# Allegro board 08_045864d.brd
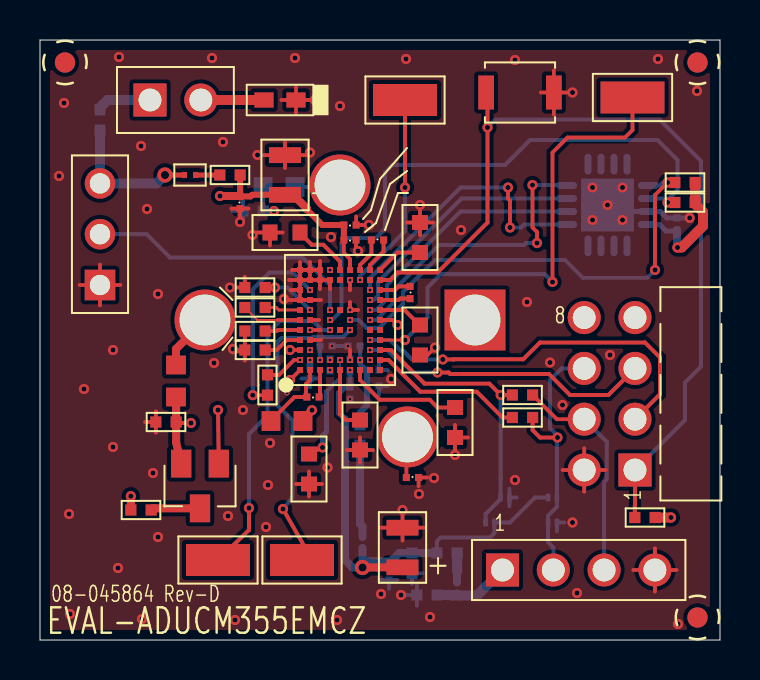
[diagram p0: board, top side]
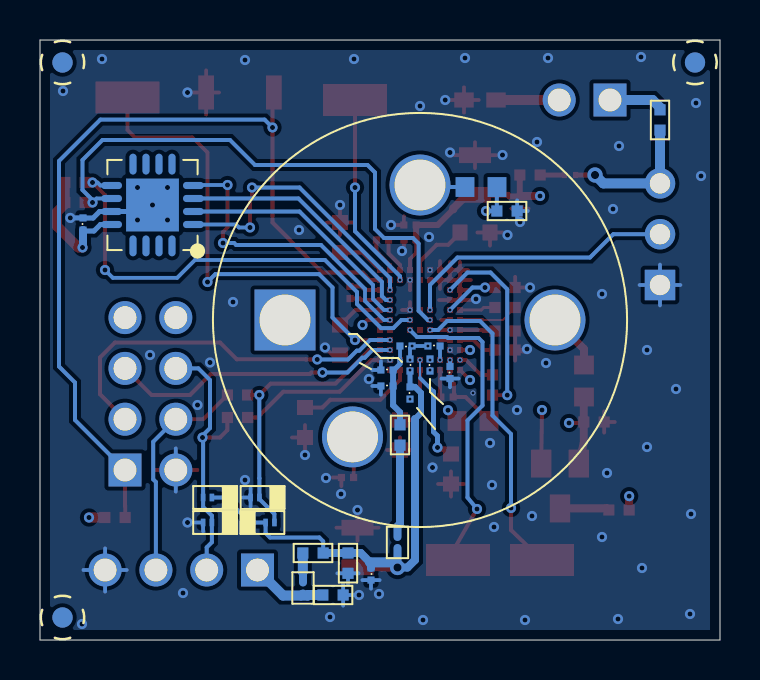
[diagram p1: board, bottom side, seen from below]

Outline 34 x 30 mm; copper layers: TOP, LAYER_2, LAYER_3, BOTTOM. Coordinates in mm from the lower left corner of the outline.
Outline path: 0,30 0,0 34,0 34,30 0,30

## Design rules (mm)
constraint set DEFAULT: min track width 0.19

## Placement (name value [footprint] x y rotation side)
C1  0.1uF  [C0201]  13.65 12.15 180 top
C2  0.1uF  [C0201]  18.62 8.12 0 top
C3  30PF  [C0402]  6.3 10.9 180 top
C4  30PF  [C0402]  10.65 21.45 0 bottom
C5  0.1uF  [C0201]  14.5 13.75 90 bottom
C6  4.7uF  [C0402]  10.75 14.5 0 top
C7  4.7uF  [CPL0805]  18.12 4.62 90 top
C8  0.1uF  [C0201]  15.5 13.75 270 bottom
C9  0.1uF  [C0201]  16.65 13.5 180 bottom
C10  0.1uF  [C0201]  15.5 20 180 top
C11  4.7uF  [CPL0805]  12.25 23.25 90 top
C12  220PF  [C0402]  10.75 17.62 0 top
C13  0.47uF  [C0603]  12.25 20.38 180 top
C14  4.7uF  [C0402]  10.75 15.45 0 top
C15  0.1uF  [C0201]  14.3 14.7 180 bottom
C16  0.1uF  [C0201]  13.5 13.38 90 bottom
C17  0.47uF  [C0603]  13.45 8.55 270 top
C18  0.47uF  [C0603]  20.75 10.88 270 top
C19  0.47uF  [C0603]  16 10.25 270 top
C20  0.1uF  [C0201]  16.88 20 0 top
C21  0.1uF  [C0201]  18.5 17.38 270 top
C22  0.47uF  [C0603]  19 20.12 270 top
C23  0.47uF  [C0603]  19 15 90 top
C24  4.7UF  [C0402]  18.6 3.84 270 bottom
C25  0.1uF  [C0201]  17.45 3.3 270 bottom
C26  0.1uF  [C0201]  16.65 12.7 180 bottom
C27  0.1uF  [C0201]  10 21.88 90 top
C28  0.1uF  [C0201]  31.85 20.8 90 bottom
C29  1000PF  [C0201]  15.5 12.35 90 bottom
C30  1000PF  [C0201]  15.7 14.7 0 bottom
C31  1000PF  [C0201]  15.5 20.75 180 top
C32  0.47uF  [C0402]  19.35 2.25 180 bottom
D1  SESD0201X1UN-0020-09  [D0201]  25.62 7.12 0 bottom
D2  SESD0201X1UN-0020-09  [D0201]  25.62 5.88 0 bottom
D3  SESD0201X1UN-0020-09  [D0201]  22.5 5.88 180 bottom
D4  SESD0201X1UN-0020-09  [D0201]  23.25 7.12 0 bottom
DS1  SML-310MTT86  [LED0603]  12 27 180 top
E1  600OHM AT 100MEGHZ  [L0201H13]  7.5 23.25 0 top
E2  600OHM AT 100MEGHZ  [L0201H13]  16.12 4.88 90 bottom
E3  600OHM AT 100MEGHZ  [L0603]  12.35 10.95 0 top
E4  600OHM AT 100MEGHZ  [L0603]  6.8 12.95 270 top
E5  600OHM AT 100MEGHZ  [L0603]  11.95 22.65 180 bottom
E6  600OHM AT 100MEGHZ  [L0201H13]  20.85 2.6 90 bottom
JP1  22-03-2031  [CNHDR1X3H530]  3 17.75 90 top
M1  CO-A4  [MCO-A4_SKTLD98]  15 16 180 bottom
NOREF  -  [unnamed]  32.88 1.12 0 top
NOREF#2  -  [#2]  0 30 270 top
NOREF#3  -  [#2]  -70 110 0 top
NOREF#4  -  [#2]  -50 -35 0 top
NOREF#5  -  [#2]  0 0 0 top
NOREF#6  -  [#2]  18 45 0 top
NOREF#7  -  [#2]  -65 -110 0 top
NOREF#8  -  [#2]  85 -50 0 top
NOREF#9  -  [#2]  34 30 180 top
NOREF#10  -  [#2]  14.08 20.92 0 top
NOREF#11  -  [#2]  -65 -110 0 top
NOREF#12  -  [#2]  0 0 90 top
NOREF#13  -  [unnamed]  32.88 28.88 0 top
NOREF#14  -  [#2]  34 0 90 top
NOREF#15  -  [#2]  0 30 0 top
NOREF#16  -  [unnamed]  1.25 28.88 0 top
NOREF#17  -  [unnamed]  1.25 28.88 180 bottom
NOREF#18  -  [unnamed]  32.88 1.12 180 bottom
NOREF#19  -  [unnamed]  32.88 28.88 180 bottom
P1  TSW-104-25-F-D-RA  [CNHDRRA2X4H240_B]  29.75 8.5 90 top
P2  961104-6404-AR  [CNHDR1X4H323]  23.12 3.5 0 top
P5  M20-9990246  [CNHARWIN-M20-9990246]  5.5 27 0 top
Q1  MMBFJ270  [SOT23]  8 7.7 180 top
R1  100K  [R0402]  5.05 6.5 0 top
R2  1K  [R0402]  24.12 12.25 180 top
R3  1K  [R0402]  24.12 11.12 180 top
R4  200  [R0402]  10.75 16.62 180 top
R5  0  [R0402]  20.35 4.35 180 bottom
R6  10K  [R0402]  32.25 21.88 180 top
R7  0  [R0402]  30.25 6.12 0 top
R8  0  [R0402]  11.38 12.75 270 top
R9  10K  [R0402]  32.25 22.88 0 top
R10  560  [R0402]  3 26 90 bottom
R11  1.6  [R0402]  16 10.25 90 bottom
R12  1.6  [R0402]  9.5 23.25 0 top
S1  B3U-1000P  [SWSML118W98H69]  24 27.38 0 top
TP1  HK-1-G  [CNTP1206]  13.1 4 0 top
TP2  HK-1-G  [CNTP1206]  18.25 27 0 top
TP3  HK-1-G  [CNTP1206]  29.62 27.12 0 top
TP4  HK-1-G  [CNTP1206]  8.9 4 0 top
U1  ADUCM355  [LGA72_5X6]  15 16 0 top
U2  ADT7320UCPZ  [QFN16_4X4_PAD2_65X2_65]  28.38 21.75 90 bottom

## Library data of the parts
C1 C2 C5 C8-C10 C15 C16 C20 C21 C25-C28 = CAP: Tolerance: 10; User Part Number: UPN; alternate symbols: (); part number: CAP_SM-0.1UF,6.3V,10,E011567,C0201; tolerance: 10
C3 C4 = CAP: User Part Number: UPN; Tolerance: 1; alternate symbols: (); part number: CAP_SM-30PF,50V,1,E023309,C0402; tolerance: 1
C6 C14 = CAP: User Part Number: UPN; Tolerance: 10; alternate symbols: (); part number: CAP_SM-4.7UF,6.3V,10,E020089,C0402; tolerance: 10
C7 C11 = CAPP: Tolerance: N/A; User Part Number: UPN; alternate symbols: (); part number: CAPP_SM-4.7UF,N/A,N/A,E020900,CPL0805; tolerance: N/A
C12 = CAP: User Part Number: UPN; Tolerance: 5; alternate symbols: (); part number: CAP_SM-220PF,50V,5,E027540,C0402; tolerance: 5
C13 C17-C19 C22 C23 = CAP: User Part Number: UPN; Tolerance: 10; alternate symbols: (); part number: CAP_SM-0.47UF,25V,10,E010966,C0603; tolerance: 10
C24 = CAP: User Part Number: UPN; Tolerance: 20; alternate symbols: (); part number: CAP_SM-4.7UF,6.3V,20,E025260,C0402; tolerance: 20
C29-C31 = CAP: Tolerance: 5; User Part Number: UPN; alternate symbols: (); part number: CAP_SM-1000PF,25V,5,E028646,C0201; tolerance: 5
C32 = CAP: User Part Number: UPN; Tolerance: 10; alternate symbols: (); part number: CAP_SM-0.47UF,6.3V,10,E021888,C0402; tolerance: 10
D1-D4 = DIO: Tolerance: N/A; User Part Number: UPN; alternate symbols: (); part number: DIO_SM-SESD0201X1UN-0020-09,9V,N/A,E022225,D0201; tolerance: N/A
DS1 = DIOLED: Tolerance: N/A; User Part Number: UPN; alternate symbols: (); part number: DIOLED_SM-SML-310MTT86,2.8V,N/A,E001179,LED0603; tolerance: N/A
E1 E2 E6 = FERRITE: Tolerance: 25; User Part Number: UPN; alternate symbols: (); part number: FERRITE_SM-600OHM AT 100MEGHZ,25,E024592,L0201H13; tolerance: 25
E3-E5 = FERRITE: User Part Number: UPN; Tolerance: 25; alternate symbols: (); part number: FERRITE_SM-600OHM AT 100MEGHZ,25,E029146,L0603; tolerance: 25
JP1 = CN3P_JMPRSHRT: User Part Number: UPN; Tolerance: N/A; alternate symbols: (CNHDR1X3H530_ALT); part number: CN3P_JMPRSHRT_TH-22-03-2031,E021002,CNHDR1X3H530; tolerance: N/A
M1 = MOD_CO_XX_V2: User Part Number: UPN; Tolerance: N/A; alternate symbols: (); part number: MOD_CO_XX_V2_TH-CO-A4,E025025,MCO-A4_SKTLD98; tolerance: N/A
P1 = CN8P_ODD_EVEN: User Part Number: UPN; Tolerance: N/A; alternate symbols: (); part number: CN8P_ODD_EVEN_TH-TSW-104-25-F-D-RA,E018544,CNHDRRA2X4H240_B; tolerance: N/A
P2 = CN4P: User Part Number: UPN; Tolerance: N/A; alternate symbols: (); part number: CN4P_TH-961104-6404-AR,E024347,CNHDR1X4H323; tolerance: N/A
P5 = CN2P: Tolerance: N/A; User Part Number: UPN; alternate symbols: (); part number: CN2P_TH-M20-9990246,E010843,CNHARWIN-M20-9990246; tolerance: N/A
Q1 = TRANPJFET: User Part Number: UPN; Tolerance: N/A; alternate symbols: (); part number: TRANPJFET_SM-MMBFJ270,E020756,SOT23; tolerance: N/A
R1 = RES: User Part Number: UPN; Tolerance: 5; alternate symbols: (); part number: RES_SM-100K,E027220,1/16W,5,R0402; tolerance: 5
R2 R3 = RES: User Part Number: UPN; Tolerance: 5; alternate symbols: (); part number: RES_SM-1K,E020936,1/16W,5,R0402; tolerance: 5
R4 = RES: User Part Number: UPN; Tolerance: 0.1; alternate symbols: (); part number: RES_SM-200,E006431,1/16W,0.1,R0402; tolerance: 0.1
R5 R7 R8 = RES: User Part Number: UPN; Tolerance: 1; alternate symbols: (); part number: RES_SM-0,E010661,1/16W,1,R0402; tolerance: 1
R6 R9 = RES: User Part Number: UPN; Tolerance: 5; alternate symbols: (); part number: RES_SM-10K,E019640,1/16W,5,R0402; tolerance: 5
R10 = RES: User Part Number: UPN; Tolerance: 1; alternate symbols: (); part number: RES_SM-560,E016560,1/10W,1,R0402; tolerance: 1
R11 R12 = RES: User Part Number: UPN; Tolerance: 1; alternate symbols: (); part number: RES_SM-1.6,E014755,1/16W,1,R0402; tolerance: 1
S1 = SWSPST2PIN_V2: Tolerance: N/A; User Part Number: UPN; alternate symbols: (); part number: SWSPST2PIN_V2_SM-B3U-1000P,E016303,SWSML118W98H69; tolerance: N/A
TP1-TP4 = CNTP1P: Tolerance: N/A; User Part Number: UPN; alternate symbols: (); part number: CNTP1P_SM-HK-1-G,E012928,CNTP1206; tolerance: N/A
U1 = ADUCM355: Tolerance: N/A; User Part Number: UPN; alternate symbols: (SKTPLA-72LHC50A01); part number: ADUCM355_SM-ADUCM355,E028185,LGA72_5X6; tolerance: N/A
U2 = ADT7320: Tolerance: N/A; User Part Number: UPN; alternate symbols: (); part number: ADT7320_SM-ADT7320UCPZ,E014097,QFN16_4X4_PAD2_65X2_65; tolerance: N/A

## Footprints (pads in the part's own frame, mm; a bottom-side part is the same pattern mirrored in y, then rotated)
C0201
  rect 0.356x0.356 smd: 1(-0.305,0) 2(0.305,0)
C0402
  rect 0.559x0.559 smd: 1(-0.508,0) 2(0.508,0)
C0603
  rect 0.75x0.8 smd: 1(-0.75,0) 2(0.75,0)
CNHARWIN-M20-9990246
  rect 1.651x1.651 hole 1.143: 1(0,0)
  round 1.651 hole 1.143: 2(2.54,0)
CNHDR1X3H530
  rect 1.524x1.524 hole 1.016: 1(0,0)
  round 1.524 hole 1.016: 2(2.54,0) 3(5.08,0)
CNHDR1X4H323
  rect 1.651x1.651 hole 1.143: 1(0,0)
  round 1.651 hole 1.143: 2(2.54,0) 3(5.08,0) 4(7.62,0)
CNHDRRA2X4H240_B
  rect 1.651x1.651 hole 1.143: 1(0,0)
  round 1.651 hole 1.143: 2(0,2.54) 3(2.54,0) 4(2.54,2.54) 5(5.08,0) 6(5.08,2.54) 7(7.62,0) 8(7.62,2.54)
CNTP1206
  rect 3.2x1.6 smd: 1(0,0)
CPL0805
  rect 0.787x1.6 smd: N(0.991,0) P(-0.991,0)
D0201
  rect 0.229x0.381 smd: A(0.22,0) C(-0.22,0)
L0201H13
  rect 0.254x0.305 smd: 1(-0.277,0) 2(0.277,0)
L0603
  rect 0.94x0.991 smd: 1(-0.8,0) 2(0.8,0)
LED0603
  rect 0.965x0.762 smd: A(0.8,0) C(-0.8,0)
LGA72_5X6
  rect 0.3x0.3 smd: A1(-2,-2.5) A2(-2,-2) A3(-2,-1.5) A4(-2,-1) A5(-2,-0.5) A6(-2,0) A7(-2,0.5) A8(-2,1) A9(-2,1.5) A10(-2,2) A11(-2,2.5) B1(-1.5,-2.5) B2(-1.5,-2) B3(-1.5,-1.5) B4(-1.5,-1) B5(-1.5,-0.5) B6(-1.5,0) B7(-1.5,0.5) B8(-1.5,1) B9(-1.5,1.5) B10(-1.5,2) B11(-1.5,2.5) C1(-1,-2.5) C2(-1,-2) C10(-1,2) C11(-1,2.5) D1(-0.5,-2.5) D2(-0.5,-2) D5(-0.5,-0.5) D6(-0.5,0) D7(-0.5,0.5) D10(-0.5,2) D11(-0.5,2.5) E1(0,-2.5) E2(0,-2) E5(0,-0.5) E7(0,0.5) E10(0,2) E11(0,2.5) F1(0.5,-2.5) F2(0.5,-2) F5(0.5,-0.5) F6(0.5,0) F7(0.5,0.5) F10(0.5,2) F11(0.5,2.5) G1(1,-2.5) G2(1,-2) G10(1,2) G11(1,2.5) H1(1.5,-2.5) H2(1.5,-2) H3(1.5,-1.5) H4(1.5,-1) H5(1.5,-0.5) H6(1.5,0) H7(1.5,0.5) H8(1.5,1) H9(1.5,1.5) H10(1.5,2) H11(1.5,2.5) J1(2,-2.5) J2(2,-2) J3(2,-1.5) J4(2,-1) J5(2,-0.5) J6(2,0) J7(2,0.5) J8(2,1) J9(2,1.5) J10(2,2) J11(2,2.5)
MCO-A4_SKTLD98
  rect 3.048x3.048 hole 2.54: 1(-6.75,0)
  round 3.048 hole 2.54: 2(0,6.75) 3(6.75,0) 4(-3.375,-5.846)
QFN16_4X4_PAD2_65X2_65
  oval 0.356x1.041 smd: 1(-0.975,-2.045) 2(-0.325,-2.045) 3(0.325,-2.045) 4(0.975,-2.045) 9(0.975,2.045) 10(0.325,2.045) 11(-0.325,2.045) 12(-0.975,2.045)
  oval 1.041x0.356 smd: 5(2.045,-0.975) 6(2.045,-0.325) 7(2.045,0.325) 8(2.045,0.975) 13(-2.045,0.975) 14(-2.045,0.325) 15(-2.045,-0.325) 16(-2.045,-0.975)
  rect 2.642x2.642 smd: PAD(0,0)
R0402
  rect 0.559x0.559 smd: 1(-0.508,0) 2(0.508,0)
SOT23
  rect 1.016x1.397 smd: 1(-0.94,-1.118) 2(0.94,-1.118) 3(0,1.118)
SWSML118W98H69
  rect 0.787x1.702 smd: 1(-1.694,0) 2(1.694,0)
unnamed
  round 1.016 smd: (0,0)

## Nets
AVDD: C10.2(N2) C11.P C27.2(N2) C31.2(N2) R1.1 R12.2(N2) U1.F11
AVDD_DD: C9.2(N2) C26.2(N2) C30.2(N2) R11.2(N2) U1.G2
DGND: C2.2(N2) C3.2(N2) C4.1 C6.1 C7.N(N2) C8.1 C9.1 C10.1 C11.N(N2) C12.1 C13.2(N2) C14.1 C15.1 C16.1 C17.2(N2) C18.2(N2) C19.2(N2) C22.1 C23.1 C24.2(N2) C25.2(N2) C26.1 C27.1 C28.2(N2) C29.1 C30.1 C31.1 C32.2(N2) D2.A(P) D4.A(P) DS1.C JP1.1 P1.2 P2.4(N4) S1.2(B) U1.A8 U1.A9 U1.A10 U1.A11 U1.B3 U1.B4 U1.B5 U1.B6 U1.B8 U1.B10 U1.B11 U1.C10 U1.C11 U1.D10 U1.D11 U1.F2 U1.F7 U1.F10 U1.H2 U2.11 U2.PAD
DVDD: C7.P C8.2(N2) C24.1 C25.1 C28.1 C29.2(N2) D1.C D3.C E1.1 E2.1 JP1.3(S3) R5.2(N2) R6.1 R7.2(N2) R9.2(N2) R10.1 U1.F1 U1.J6 U2.12(VDD)
VBAT: C32.1 E6.1 P1.8(N8) P2.1
AIN0: R8.2(N2) U1.B9
CAP_POT0: C1.1 U1.C1
CE0: C1.2(N2) E3.1 U1.B1
CT: R6.2(N2) U1.D6 U2.10
DE0: C2.1 M1.4 R8.1 U1.A2
GPIO0: TP2.1(N1) U1.G10
INT: R9.1 U1.F6 U2.9
LPF0: C6.2(N2) U1.A4
P1.0/SYS_WAKE: TP1.1(N1) U1.F5
P1.1/BM: TP4.1(N1) U1.D5
P1.2: U1.E7
P1.3: JP1.2 U1.D7
P2.4: TP3.1(N1) U1.J4
RC0_0: C5.1 U1.D1
RC0_1: C5.2(N2) U1.D2
RE0: C3.1 E4.2(N2) Q1.2(S) U1.A1
RESET: P1.1 R7.1 S1.1 U1.J10
SE0: C4.2(N2) E5.2(N2) Q1.1 U1.A3
SIN: D1.A(P) D2.C P1.6 P2.2 R3.1
SOUT: P1.4 P2.3 R2.1
SPI0_/CS0: U1.H6 U2.4
SPI0_CLK: U1.H9 U2.1
SPI0_MISO: U1.H7 U2.2
SPI0_MOSI: U1.H8 U2.3
SWCLK: P1.5 U1.H3
SWDIO: P1.3 U1.H4
UART_SIN: R3.2(N2) U1.J2
UART_SOUT: D3.A(P) D4.C R2.2(N2) U1.J3
UNNAMED_1_ADUCM355_I167_ADCVBIA: C13.1 U1.E11
UNNAMED_1_ADUCM355_I167_AIN3: C12.2(N2) U1.B7
UNNAMED_1_ADUCM355_I167_AVDDREG: C19.1 U1.E1
UNNAMED_1_ADUCM355_I167_DVDDR_1: C18.1 U1.G1
UNNAMED_1_ADUCM355_I167_DVDDREG: C23.2(N2) U1.J7
UNNAMED_1_ADUCM355_I167_RCAL0: R4.1 U1.A7
UNNAMED_1_ADUCM355_I167_RCAL1: R4.2(N2) U1.A6
UNNAMED_1_ADUCM355_I167_VBIAS0: C15.2(N2) U1.C2
UNNAMED_1_ADUCM355_I167_VCDCCAP: C20.1 U1.G11
UNNAMED_1_ADUCM355_I167_VDCDC_1: C21.1 U1.J9
UNNAMED_1_ADUCM355_I167_VDCDC_2: C20.2(N2) U1.H11
UNNAMED_1_ADUCM355_I167_VDCDC_3: C22.2(N2) U1.J11
UNNAMED_1_ADUCM355_I167_VDCDCCA: C21.2(N2) U1.J8
UNNAMED_1_ADUCM355_I167_VREF1: C14.2(N2) U1.A5
UNNAMED_1_ADUCM355_I167_VREF2: C17.1 U1.E2
UNNAMED_1_ADUCM355_I167_VZERO0: C16.2(N2) U1.B2
UNNAMED_1_CN2P_I142_N1: P5.1 R10.2(N2)
UNNAMED_1_DIOLED_I128_P: DS1.A(P) P5.2(N2)
UNNAMED_1_FERRITE_I82_N2: E2.2(N2) R11.1
UNNAMED_1_FERRITE_I85_N2: E1.2(N2) R12.1
UNNAMED_1_FERRITE_I163_N2: E3.2(N2) M1.1
UNNAMED_1_FERRITE_I164_N1: E4.1 M1.3
UNNAMED_1_FERRITE_I165_N1: E5.1 M1.2(WE)
UNNAMED_1_FERRITE_I166_N2: E6.2(N2) R5.1
UNNAMED_1_RES_I120_N2: Q1.3 R1.2(N2)

Pads without a net: P1 7; U1 E5 E10 H1 H5 H10 J1 J5; U2 5 6 7 8 13 14 15 16

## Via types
v1: diameter 0.508, hole 0.254, TOP to BOTTOM, 100 vias
v2: diameter 0.254, hole 0.152, TOP to BOTTOM, 33 vias
v3: diameter 0.762, hole 0.406, TOP to BOTTOM, 2 vias

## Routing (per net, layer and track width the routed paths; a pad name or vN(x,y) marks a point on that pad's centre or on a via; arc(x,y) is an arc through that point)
AVDD: length 27.9
  TOP w0.19: C10.2 15.2,19.35 15.5,19.05
  TOP w0.2: U1.F11 15.5,18.93 15.5,19.05
  TOP w0.3: C11.P 10.61,22.26 10.53,22.18 C27.2 10.01,22.19 R12.2 ; 13.34,21.53 14.12,20.75 C31.2 C10.2
  TOP w0.4: R1.1 v1(4.54,7.19) ; C11.P 12.66,22.26 13.34,21.58 13.34,21.53 ; C27.2 9.98,22.2 v1(9,22.2)
  LAYER_3 w0.4: v1(4.54,7.19) 4.54,17.74 v1(9,22.2)
AVDD_DD: length 4.3
  BOTTOM w0.19: C30.2 16,14.7 v2(16,14)
  BOTTOM w0.25: C9.2 16.3,13.5 16,13.8 v2(16,14)
  BOTTOM w0.3: C9.2 C26.2 16.35,11.74 16,11.39 R11.2
DGND: length 113
  TOP w0.19: 25.69,26.27 S1.2 ; S1.2 25.05,27.38 ; S1.2 26.34,27.38 ; S1.2 25.69,28.48 ; U1.A10 12.45,18 ; U1.A10 U1.B10 ; U1.A10 U1.A11 ; U1.A10 U1.A9 ; 15.35,9.5 C19.2 ; C19.2 16,8.87 ; C19.2 16,10.13 ; C19.2 16.65,9.5 ; U1.C11 U1.B11 ; U1.C11 U1.C10 ; U1.C11 14,18.95 ; U1.B11 13.5,18.9 ; U1.B11 U1.A11 ; U1.B11 U1.B10 ; 11.5,19.72 C13.2 ; C13.2 12.13,20.38 ; C13.2 10.87,20.38 ; C3.2 5.79,11.43 ; C3.2 5.79,10.37 ; C3.2 5.26,10.9 ; 14.5,17.55 U1.D10 U1.C10 ; JP1.1 3,18.77 ; JP1.1 3,16.73 ; JP1.1 4.02,17.75 ; JP1.1 1.98,17.75 ; U1.A8 U1.A9 ; U1.A8 12.25,17 v1(12.2,17.05) ; U1.A8 U1.B8 14.05,17 ; U1.A9 12.53,17.5 ; 15.8,21.18 C31.1 16.24,20.75 ; 9.71,17.62 C12.1 10.24,18.16 ; 18.93,7.69 C2.2 19.36,8.12 ; 11.2,24.24 C11.N ; C11.N 12.25,23.59 ; C11.N 12.25,24.89 ; C11.N 13.3,24.24 ; 10.24,13.97 C6.1 ; C6.1 9.71,14.5 ; C6.1 C14.1 10.24,15.5 ; C6.1 9.62,14.38 ; U1.B10 U1.C10 ; U1.C10 14,17.55 ; U1.B4 14.05,15 ; 26.13,8.5 P1.2 ; P1.2 27.21,9.58 ; P1.2 28.29,8.5 ; P1.2 27.21,7.42 ; 17.07,5.62 C7.N ; C7.N 19.18,5.62 ; C7.N 18.12,6.26 ; C7.N 18.12,4.97 ; C17.2 14.1,7.8 ; C17.2 13.45,7.17 ; C17.2 12.8,7.8 ; C17.2 13.45,8.43 ; 12.8,26.37 DS1.C ; DS1.C v1(13.74,27) ; DS1.C 12.8,27.63 ; DS1.C 12.06,27 ; v1(15.9,19.45) 15.8,19.65 C10.1 ; 12.6,18.5 U1.A11 ; U1.A11 13,18.9 ; U1.B6 13.95,16 ; C18.2 21.4,10.12 ; C18.2 20.75,9.5 ; C18.2 20.75,10.75 ; C22.1 19.65,20.88 ; C22.1 19,20.25 ; C22.1 19,21.5 ; C22.1 18.35,20.88 ; C27.1 10.43,21.57 ; C27.1 10,21.14 ; C27.1 9.57,21.57 ; 15.9,16.5 v2(15.5,16.5) 15.5,16.9 ; P2.4 30.75,4.58 ; P2.4 30.75,2.42 ; P2.4 31.82,3.5 ; P2.4 29.67,3.5 ; v2(15.5,14) 15.5,14.5 ; C23.1 19.38,14.25 v1(19.75,14.62) ; 14,15.5 v2(13.5,15.5) ; 15.5,17.5 v2(15.5,18)
  LAYER_2 w0.19: JP1.1 3,18.77 ; JP1.1 3,16.73 ; JP1.1 1.98,17.75 ; JP1.1 4.02,17.75 ; 26.13,8.5 P1.2 ; P1.2 28.29,8.5 ; P1.2 27.21,9.58 ; P1.2 27.21,7.42 ; 29.67,3.5 P2.4 ; P2.4 30.75,2.42 ; P2.4 31.82,3.5 ; P2.4 30.75,4.58
  LAYER_3 w0.19: P2.4 30.75,4.58 ; P2.4 30.75,2.42 ; P2.4 29.67,3.5 ; P1.2 28.29,8.5 ; P1.2 26.13,8.5 ; P1.2 27.21,9.58 ; P1.2 27.21,7.42 ; JP1.1 4.02,17.75 ; JP1.1 3,16.73 ; JP1.1 1.98,17.75 ; JP1.1 3,18.77
  BOTTOM w0.19: C24.2 19.13,3.33 ; C24.2 18.6,2.8 ; C24.2 18.07,3.33 ; 18.31,2.25 C32.2 ; C32.2 18.84,2.78 ; C32.2 18.84,1.72 ; 1.98,17.75 JP1.1 ; JP1.1 4.02,17.75 ; JP1.1 3,18.77 ; JP1.1 3,16.73 ; 17.02,3 C25.2 ; C25.2 17.45,2.56 ; C25.2 17.88,3 ; 9.61,21.45 C4.1 ; C4.1 10.14,20.92 ; C4.1 10.14,21.98 ; 16.95,13.93 C9.1 17.39,13.5 ; C16.1 13.93,13.07 ; C16.1 13.5,12.64 ; C16.1 13.07,13.07 ; 17.39,12.7 C26.1 16.95,12.27 ; 23.47,6.68 D4.A ; D4.A 23.84,7.12 ; D4.A 23.47,7.57 ; 26.21,5.88 D2.A 25.84,5.43 ; 30.75,2.42 P2.4 ; P2.4 29.67,3.5 ; P2.4 31.82,3.5 ; P2.4 30.75,4.58 ; C8.1 v2(15.5,14) 15.5,14.6 v2(15.4,14.7) v2(14.6,14.7) ; 27.21,7.42 P1.2 27.21,9.58
  BOTTOM w0.25: v1(28.38,21.75) 29.2,21.75 29.52,21.42 U2.11 31.02,21.42 31.34,21.1 31.85,21.1 C28.2 v1(32.48,21.1)
  vias: v1(0.95,23.2) v1(1.2,26.85) v1(1.45,6.3) v1(1.5,1.3) v1(2.2,12.55) v1(3.65,14.5) v1(3.65,9.65) v1(3.9,3.6) v1(3.95,29.15) v1(5.05,24.7) v1(5.1,1.05) v1(5.35,21.55) v1(5.65,8.35) v1(5.9,17.3) v1(5.9,5.15) v1(8.6,29.1) v1(8.7,13.85) v1(9.15,24.9) v1(9.4,6.2) v1(9.5,17.62) v1(9.65,14.55) v1(9.75,1) v1(10,20.9) v1(10.15,11.5) v1(10.62,20.25) v1(10.88,24.25) v1(11.3,5.65) v1(11.4,7.75) v1(11.5,9.85) v1(12.75,29.1) v1(13.5,24.38) v1(14.38,8.62) v1(14.55,20.15) v1(14.85,1) v1(15,26.7) v1(16.45,20.75) v1(17.05,2.3) v1(17.56,13.05) v1(18.12,6.5) v1(18.05,2.25) v1(18.3,29.05) v1(18.95,7.3) v1(19,21.75) v1(19.5,1.15) v1(19.7,8.1) v1(20.75,9.25) v1(21.05,20.5) v1(23.75,29) v1(23.75,8) v1(24.35,16.9) v1(25.5,13.88) v1(26.12,11.75) v1(26.62,27.38) v1(26.62,5.88) v1(26.85,2.35) v1(27.62,22.62) v1(27.62,21) v1(28.5,14.25) v1(29.12,22.62) v1(29.12,21) v1(30.9,29.05) v1(31.9,0.8) v1(32.85,27.45) v2(12.35,12.35) v2(13.5,14.5) v2(14.5,18.5) v2(15.5,12.05) v2(16.5,14)
DVDD: length 113.4
  TOP w0.2: U1.J6 17.62,16 v1(17.88,15.75)
  TOP w0.25: v3(6.25,23.25) E1.1
  TOP w0.4: v3(16.12,3.62) 16.91,3.62 16.92,3.63 C7.P
  TOP w0.5: R9.2 R6.1 32.76,21.79 33.15,21.4 33.15,20.69 32.08,19.62 v1(31.88,19.62) ; R7.2 v1(31.55,6.12)
  LAYER_3 w0.4: v2(15.5,13.5) 15.88,13.12 16.37,13.12 17.38,14.13 17.38,15.5 17.62,15.75 v1(17.88,15.75)
  LAYER_3 w0.5: 32.3,6.15 32.3,2.7 30.95,1.35 22.15,1.35 19.88,3.62 v3(16.12,3.62) 5.83,3.62 1.25,8.2 1.25,21.7 2.38,22.83 JP1.3 ; 32.3,6.15 32.3,19.2 v1(31.88,19.62) ; 32.3,6.15 32.27,6.12 v1(31.55,6.12)
  BOTTOM w0.2: R5.2 19.84,4.93 20.03,5.12 22.5,5.12 22.72,5.34 D3.C 23.5,5.88 24.75,7.12 D1.C
  BOTTOM w0.25: C28.1 31.8,20.45 31.3,20.45 30.98,20.77 30.76,20.77 ; C29.2 C8.2
  BOTTOM w0.3: 15.25,11.05 14.95,11.35 14.95,12.35 15.25,12.65 C29.2 ; 30.76,20.77 U2.12
  BOTTOM w0.4: R5.2 C24.1 17.97,4.35 17.45,3.83 C25.1 ; 15.25,11.05 15.25,4 15.62,3.62 v3(16.12,3.62) E2.1 ; C28.1 31.85,19.65 v1(31.88,19.62)
  BOTTOM w0.5: v3(6.25,23.25) 5.83,22.83 JP1.3 R10.1 ; 17.5,3.88 16.38,3.88 v3(16.12,3.62)
VBAT: length 19.1
  LAYER_3 w0.5: P2.1 23.12,5.25 24.62,6.75 24.62,15 25.75,16.12 P1.8
  BOTTOM w0.4: 20.95,2.22 E6.1
  BOTTOM w0.5: P2.1 21.85,2.22 20.62,2.22 20.59,2.25 C32.1
AIN0: length 9.6
  TOP w0.19: v1(10.64,12.24) R8.2
  BOTTOM w0.2: v2(13.5,17.5) 12.62,18.38 11.47,18.38 10.64,17.54 v1(10.64,12.24)
CAP_POT0: length 1.4
  TOP w0.19: U1.C1 14,12.95
  TOP w0.2: C1.1 14,12.2 14,12.95
CE0: length 3.8
  TOP w0.19: 13.5,13 U1.B1 ; E3.1 11.55,10.98 12.59,12.01
  TOP w0.2: 13.5,13 13.3,12.8 13.3,12.2 C1.2 12.72,12.15 12.59,12.01
CT: length 28.8
  TOP w0.19: v1(31.38,21.88) R6.2
  BOTTOM w0.19: v1(31.38,21.88) 31.17,22.08 U2.10
  BOTTOM w0.2: 31.31,21.94 31.88,22.5 31.88,24 30.88,25 24.5,25 23.25,23.75 17.62,23.75 17.25,23.38 17.25,20.55 16.8,20.1 15.35,20.1 15.07,19.82 15.07,16.46 14.61,16 v2(14.5,16)
DE0: length 13.9
  TOP w0.19: v2(13,14) 12.7,14 11.95,13.25 11.38,13.25 R8.1 11.76,13.26 ; C2.1 18.32,10.1 M1.4
  LAYER_3 w0.19: v2(13,14) 13,13.8 13.4,13.4 13.4,12.65 12.6,11.85 12.6,11 13.15,10.45 15.85,10.45 M1.4
GPIO0: length 9.9
  TOP w0.2: v1(18.25,22.62) TP2.1
  BOTTOM w0.2: v1(18.25,22.62) 18.25,20.44 16,18.19 v2(16,18)
INT: length 23.7
  TOP w0.19: R9.1 v1(31.38,22.88) 30.75,22.25 v1(30.75,18.5)
  BOTTOM w0.19: v1(30.75,18.5) 30.36,18.11 27.14,18.11 26.25,19 24.75,19 ; v1(31.38,22.88) 31.12,22.88 30.98,22.73 U2.9
  BOTTOM w0.2: 24.75,19 19.75,19 18.15,17.4 18.15,16.8 16.94,15.59 16.34,15.59 15.93,16 v2(15.5,16)
LPF0: length 1.9
  TOP w0.19: U1.A4 12.34,15 11.84,14.5 C6.2
P1.0/SYS_WAKE: length 15.6
  TOP w0.2: v1(12.15,6.55) 13.23,4.67 13.3,4.29 TP1.1
  BOTTOM w0.2: v2(15.5,15.5) 15.15,15.15 13.65,15.15 13.6,15.1 12.07,15.1 11.88,14.9 11.88,11.73 12.62,10.98 12.62,7.12 v1(12.15,6.55)
P1.1/BM: length 15.9
  TOP w0.2: v1(10.45,6.6) 10.45,5.5 TP4.1
  BOTTOM w0.2: v1(10.45,6.6) 10.45,10.3 11.38,11.22 11.38,15.32 12,15.95 13.64,15.95 14.09,15.5 v2(14.5,15.5)
P1.3: length 13.8
  BOTTOM w0.2: JP1.2 5.33,20.29 6.5,19.12 13.12,19.12 14.5,17.75 v2(14.5,16.5)
P2.4: length 24.7
  TOP w0.15: v1(18.25,15) U1.J4
  TOP w0.19: v1(25.62,17.9) 25.62,24.38 26.38,25.12 29.25,25.12 29.62,25.5 TP3.1
  TOP w0.2: 30.62,26.62 TP3.1
  BOTTOM w0.2: v1(25.62,17.9) 25.23,18.29 20.04,18.29 19.38,17.62 19.38,16.12 v1(18.25,15)
RC0_0: length 0.1
  BOTTOM w0.25: v2(14.5,13.5) C5.1
RC0_1: length 0.1
  BOTTOM w0.25: v2(14.5,14) C5.2
RE0: length 11.4
  TOP w0.19: U1.A1 v1(12.5,13)
  TOP w0.2: C3.1 6.86,10.85 v1(7.55,10.85)
  TOP w0.4: E4.2 6.81,12.14 C3.1 6.81,9.87 Q1.2
  LAYER_3 w0.19: 9.15,10.85 9.55,11.25 9.55,11.85 11.2,13.5 12,13.5 v1(12.5,13)
  LAYER_3 w0.2: 9.15,10.85 v1(7.55,10.85)
RESET: length 44
  TOP w0.2: P1.1 29.75,6.72 29.74,6.71 R7.1 ; S1.1 22.38,27.31 v1(22.38,25.62) 22.38,20.88 19.88,18.38 17.88,18.38 17.5,18 U1.J10
  BOTTOM w0.2: P1.1 32.25,11 32.25,12.87 33.05,13.67 33.05,23.95 30.98,26.02 22.77,26.02 v1(22.38,25.62)
SE0: length 17.5
  TOP w0.19: U1.A3 v1(12.5,14.5)
  TOP w0.2: Q1.1 v1(8.9,11.5)
  LAYER_3 w0.2: v1(8.9,11.5) 8.94,11.99 10.8,13.85 11.85,13.85 v1(12.5,14.5) 12.75,14.75 12.75,17.7 11.7,18.75 v1(11.7,21.45)
  BOTTOM w0.2: v1(11.7,21.45) C4.2 11.16,22.64 E5.2
SIN: length 14
  TOP w0.2: R3.1 24.63,10.49 25,10.12 v1(25.88,10.12)
  BOTTOM w0.2: v1(25.88,10.12) 25.88,10.22 25.84,10.25 ; P1.6 26.08,13.58 25.5,13 25.5,10.6 25.84,10.25 ; 25.84,10.25 D1.A 25.84,6.66 25.41,6.21 D2.C 25.41,4.89 25.66,4.63 P2.2
SOUT: length 11.1
  TOP w0.19: P1.4 25.84,11.04 R2.1
  BOTTOM w0.2: P1.4 28.34,9.91 28.34,8.03 28.2,7.9 P2.3
SPI0_/CS0: length 15
  TOP w0.19: v1(24.62,22.75) 24.62,20.63 24.85,20.4 v1(24.85,19.85)
  BOTTOM w0.19: v2(16.5,16) 16.8,16 17.75,16.95 17.75,17.55 ; U2.4 25.91,22.73 25.89,22.75 v1(24.62,22.75)
  BOTTOM w0.2: 17.75,17.55 19.95,19.75 24.19,19.75 24.29,19.85 v1(24.85,19.85)
SPI0_CLK: length 14.3
  TOP w0.19: v1(23.4,22.62) 23.4,22.07 23.5,21.97 v1(23.5,20.62)
  BOTTOM w0.19: U2.1 24.2,20.77 24.05,20.62 v1(23.5,20.62)
  BOTTOM w0.2: v2(16.5,17.5) 16.5,18.1 21.02,22.62 v1(23.4,22.62)
SPI0_MISO: length 12.3
  BOTTOM w0.19: 17.35,17.75 17.35,17.05 16.8,16.5 v2(16.5,16.5)
  BOTTOM w0.2: U2.2 21.02,21.42 17.35,17.75
SPI0_MOSI: length 12.3
  BOTTOM w0.2: v2(16.5,17) 16.71,17 16.91,17.2 16.91,17.91 21.08,22.08 U2.3
SWCLK: length 14.7
  TOP w0.2: v1(19.88,13.38) 20.43,13.38 20.51,13.3 25.45,13.3 26.5,12.25 28.42,12.25 P1.5
  BOTTOM w0.2: v2(16.5,14.5) 17.38,14.5 17.76,14.11 17.89,14.11 18.62,13.38 v1(19.88,13.38)
SWDIO: length 19.2
  TOP w0.2: v1(20.14,14.03) 20.7,14.03 20.7,14.04 24.16,14.04 25,14.88 30.25,14.88 31,14.12 31,12.29 P1.3
  BOTTOM w0.2: v2(16.5,15) 17.5,15 18.03,14.47 18.16,14.47 18.6,14.03 v1(20.14,14.03)
UART_SIN: length 7.8
  TOP w0.2: R3.2 23.12,11.12 21.84,12.41 19.02,12.41 17.43,14 U1.J2
UART_SOUT: length 14.2
  TOP w0.15: 18.39,13.65 18.45,13.6
  TOP w0.2: R2.2 v1(23.03,12.25) 22.47,12.82 19.23,12.82 18.45,13.6 ; 18.39,13.65 17.55,14.5 U1.J3
  BOTTOM w0.2: v1(23.03,12.25) 23.03,8.09 23.03,8.09 D4.C 23.03,7.05 22.28,6.3 D3.A
UNNAMED_1_ADUCM355_I167_ADCVBIA: length 3
  TOP w0.2: C13.1 13,20.35 13.59,19.76 14.17,19.76 15,18.93 U1.E11
UNNAMED_1_ADUCM355_I167_AIN3: length 2.7
  TOP w0.15: v1(11.75,17.62) C12.2
  BOTTOM w0.2: v1(11.75,17.62) 12.38,17.62 v2(13.5,16.5)
UNNAMED_1_ADUCM355_I167_AVDDREG: length 3.3
  TOP w0.2: U1.E1 15,11.3 15.3,11 C19.1
UNNAMED_1_ADUCM355_I167_DVDDR_1: length 5.8
  TOP w0.2: U1.G1 16,13 16.99,12.01 19.49,12.01 19.88,11.62 C18.1
UNNAMED_1_ADUCM355_I167_DVDDREG: length 2.3
  TOP w0.2: C23.2 18.98,15.75 18.22,16.5 U1.J7
UNNAMED_1_ADUCM355_I167_RCAL0: length 1.8
  TOP w0.15: U1.A7 11.94,16.5 11.82,16.62 R4.1
UNNAMED_1_ADUCM355_I167_RCAL1: length 3
  TOP w0.1: 11.88,16 10.87,16 R4.2
  TOP w0.19: U1.A6 11.88,16
UNNAMED_1_ADUCM355_I167_VBIAS0: length 0.7
  BOTTOM w0.19: C15.2 14,14.7 v2(14,14)
UNNAMED_1_ADUCM355_I167_VCDCCAP: length 1.7
  TOP w0.2: C20.1 16.57,19.32 16,18.75 U1.G11
UNNAMED_1_ADUCM355_I167_VDCDC_1: length 1.6
  TOP w0.2: U1.J9 17.75,17.5 17.93,17.68 C21.1
UNNAMED_1_ADUCM355_I167_VDCDC_2: length 1.8
  TOP w0.2: C20.2 17.18,19.43 16.5,18.75 U1.H11
UNNAMED_1_ADUCM355_I167_VDCDC_3: length 2.4
  TOP w0.2: U1.J11 17.87,19.38 C22.2
UNNAMED_1_ADUCM355_I167_VDCDCCA: length 1.5
  TOP w0.2: C21.2 18,17.07 17.93,17 U1.J8
UNNAMED_1_ADUCM355_I167_VREF1: length 1.8
  TOP w0.19: C14.2 11.84,15.45 11.89,15.5 U1.A5
UNNAMED_1_ADUCM355_I167_VREF2: length 5.5
  TOP w0.19: C17.1 v1(14.12,9.62)
  BOTTOM w0.1: 15,13.1 v2(15,14)
  BOTTOM w0.19: 14.32,12.43 15,13.1
  BOTTOM w0.25: v1(14.12,9.62) 14.12,10.21 14.32,10.41 14.32,12.43
UNNAMED_1_ADUCM355_I167_VZERO0: length 0.3
  BOTTOM w0.19: v2(13.5,14) C16.2
UNNAMED_1_CN2P_I142_N1: length 2.8
  BOTTOM w0.5: R10.2 3,26.62 3.38,27 P5.1
UNNAMED_1_DIOLED_I128_P: length 3.2
  TOP w0.5: P5.2 DS1.A
UNNAMED_1_FERRITE_I82_N2: length 4.6
  BOTTOM w0.4: R11.1 16,5.81 16.12,5.68 E2.2
UNNAMED_1_FERRITE_I85_N2: length 1.2
  TOP w0.25: E1.2 R12.1
UNNAMED_1_FERRITE_I163_N2: length 12
  TOP w0.4: E3.2 13.15,11.04 v1(13.6,11.49)
  LAYER_3 w0.19: M1.1 21.75,13.8 20.4,12.45 17.1,12.45 16.14,11.49 v1(13.6,11.49)
UNNAMED_1_FERRITE_I164_N1: length 2.9
  TOP w0.4: M1.3 6.8,14.55 E4.1
UNNAMED_1_FERRITE_I165_N1: length 2.3
  BOTTOM w0.2: E5.1 14.9,22.65 M1.2
UNNAMED_1_FERRITE_I166_N2: length 1.5
  BOTTOM w0.4: E6.2 20.85,3.41 20.86,3.42
  BOTTOM w0.5: 20.86,3.42 R5.1
UNNAMED_1_RES_I120_N2: length 2.5
  TOP w0.4: Q1.3 5.64,6.58 R1.2

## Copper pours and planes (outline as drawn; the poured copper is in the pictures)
DGND on TOP: 33.5,29.5 0.5,29.5 0.5,0.5 33.5,0.5 ; 1 cut-out
DGND on BOTTOM: 0.5,29.5 33.5,29.5 33.5,0.5 0.5,0.5 ; 1 cut-out
DGND on LAYER_2: 0.25,29.75 33.75,29.75 33.75,0.25 0.25,0.25
DGND on LAYER_3: 33.75,29.75 0.25,29.75 0.25,0.25 33.75,0.25

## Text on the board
Ref Des/Silkscreen Top: 08-045864 Rev-D | EVAL-ADUCM355EMCZ
User.17: L2 GROUND PLANE | 08-      -07
User.18: L3 GROUND PLANE | 08-      -08
User.45: 1. Material: 4 Layer FR4 glass epoxy laminate 1.6mm +/- 10%. | 2. Plated thru holes and conductive pattern electroplated with 0.255mm min. thick copper. | 3. Processing tolerence: | 4. Warp and twist within 0.1875mm per 25mm (0.75%) | 5. Dimensions are for the finished part. | 6. SOLDERMASK: liquid Photo Imeagable soldermask over bare copper (SMOBC), | 7. SCREENING: Screen component outlines and nomenclature using indelible white ink on both sides. | 8. Electrically test 100%. | 9. Break all sharp edges 0.35mm Radius max. | 10. | 11. The 0.1524mm via holes (x33) are to be filled with conductive material and finished planar on Top side. | Board to be fabricated per IPC-6012A, CLASS 2. | Finished board shall be REACH & RoHS compliant. | Terminal areas and plated thru holes to be ENIG plated. | A. Conductive pattern front to back registration within 0.125mm total. | B. Minimum annual ring surrounding holes 0.05mm. | C. Finished conductive pattern to be within 0.05mm of true size. | D. Minimum feature size 0.19mm | E. Minimum air gap 0.10mm | colour GREEN both sides using the pattern provided. No mask is permitted on the terminal areas. | Soldermask to etch registration within 0.125mm total. | Nomenclature shall be legible. Screen to etch registration within 0.15mm total. | FABRICATION NOTES:
